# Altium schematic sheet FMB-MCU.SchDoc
size A3
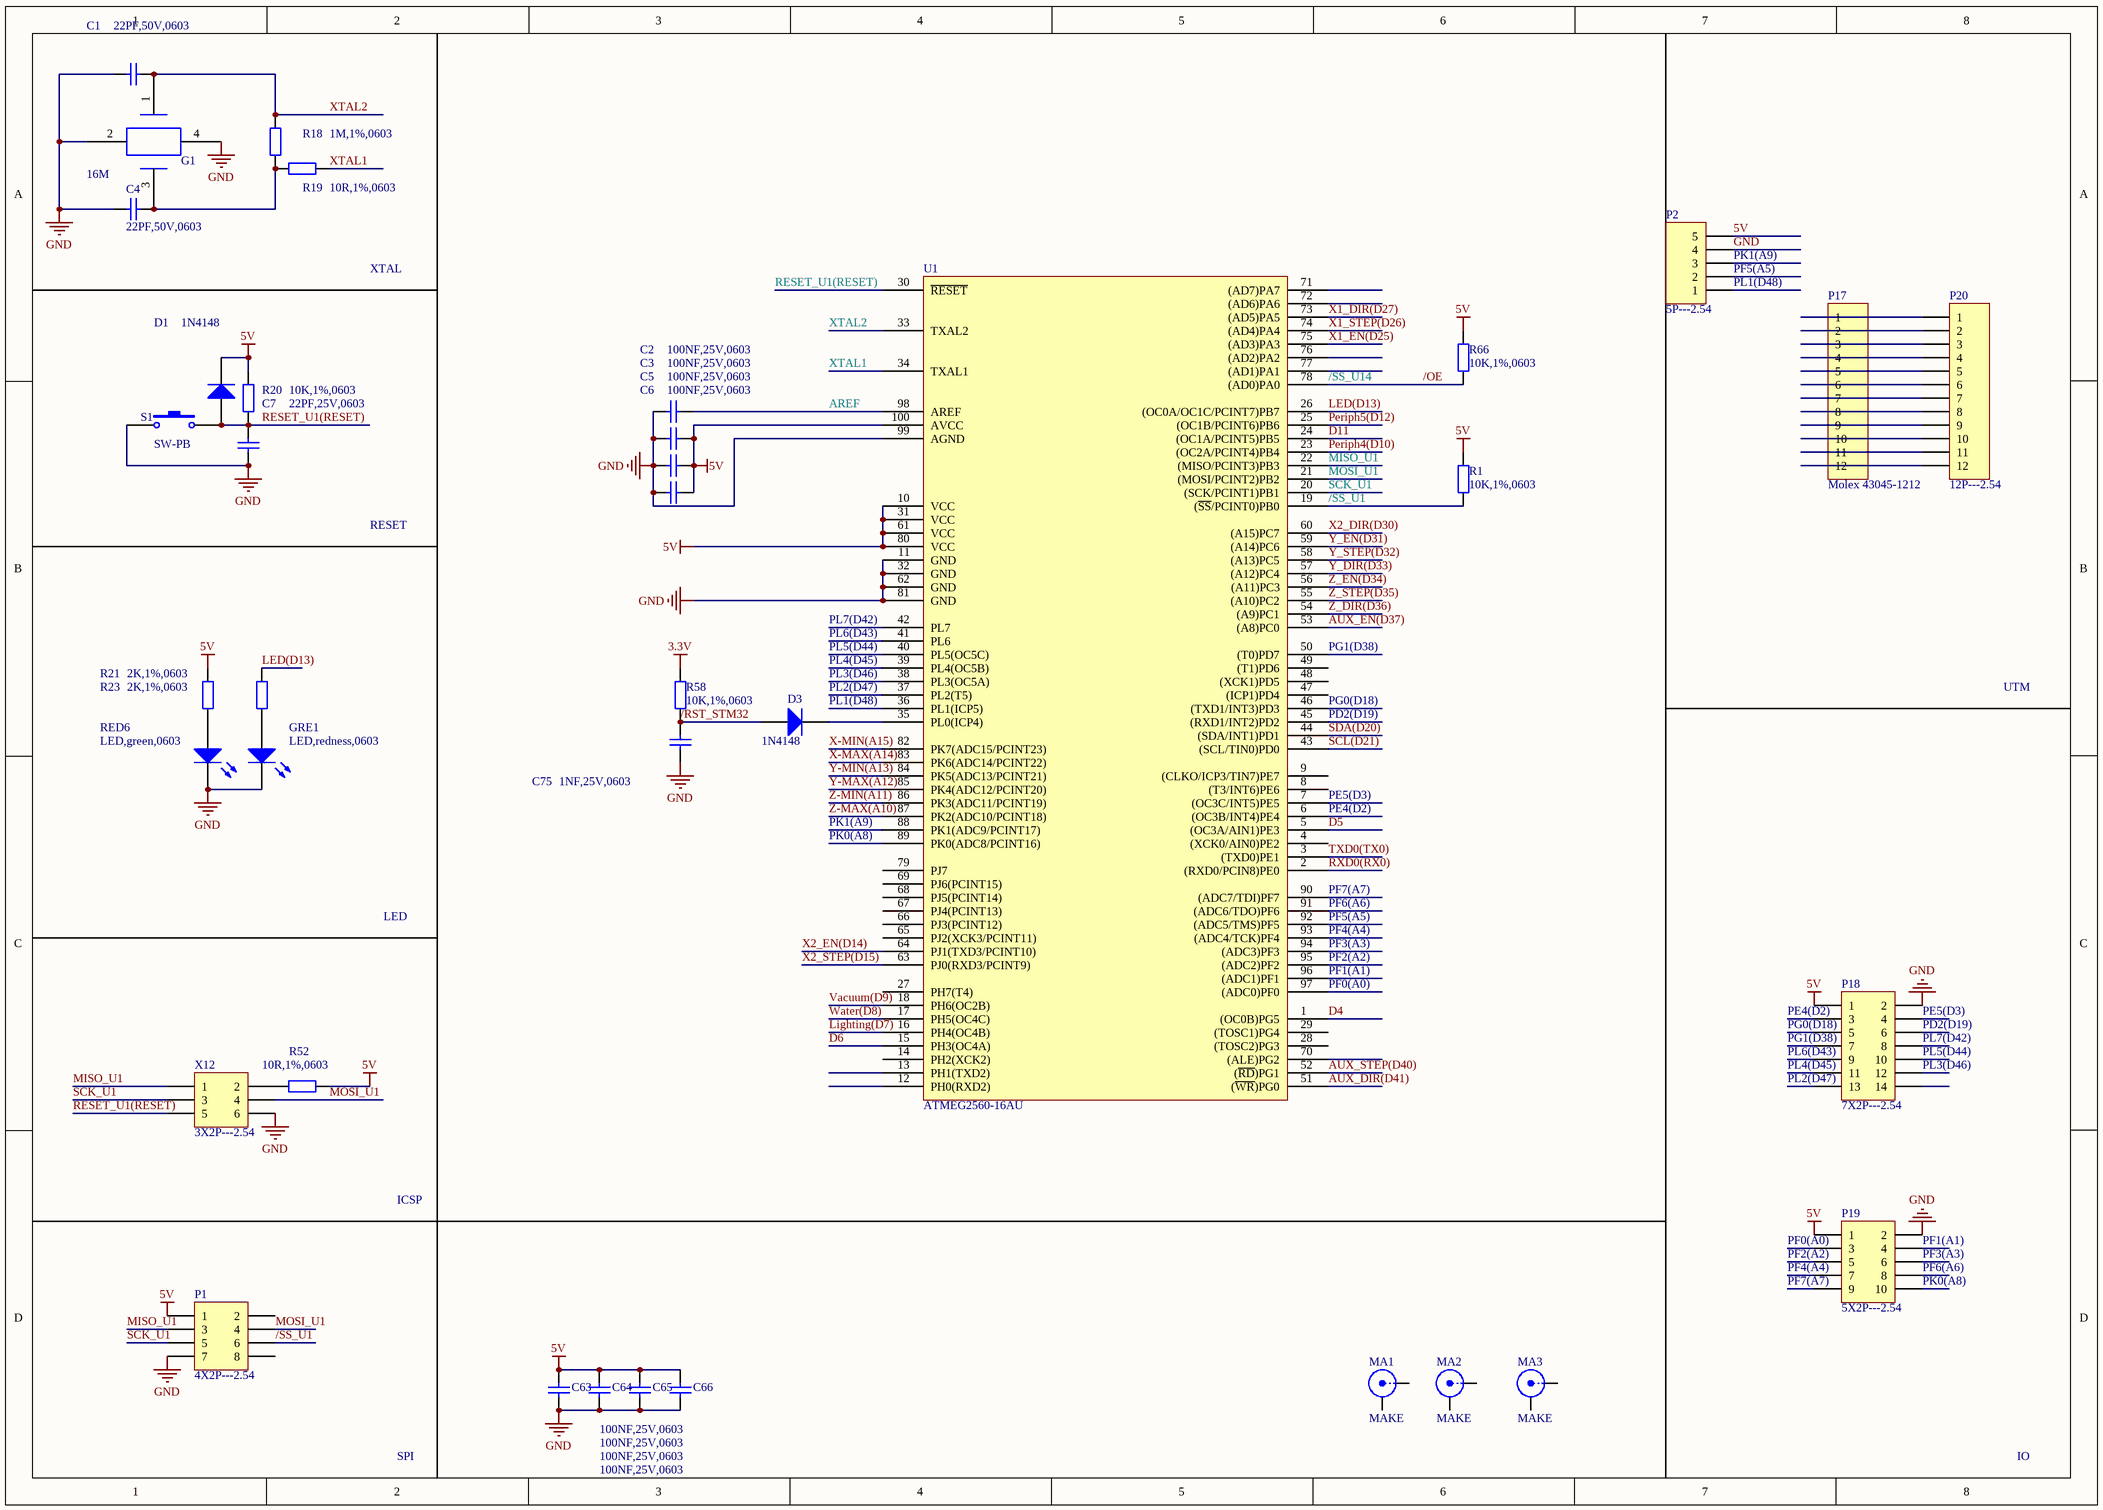
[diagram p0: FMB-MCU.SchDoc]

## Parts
C1  22PF,50V,0603  [RC0603]
C2  100NF,25V,0603  [RC0603]
C3  100NF,25V,0603  [RC0603]
C4  22PF,50V,0603  [RC0603]
C5  100NF,25V,0603  [RC0603]
C6  100NF,25V,0603  [RC0603]
C7  22PF,25V,0603  [RC0603]
C63  100NF,25V,0603  [RC0603]
C64  100NF,25V,0603  [RC0603]
C65  100NF,25V,0603  [RC0603]
C66  100NF,25V,0603  [RC0603]
C75  1NF,25V,0603  [RC0603]
D1  1N4148  [SOD-323]
D3  1N4148  [SOD-323]
G1  16M  [Y-3225]
GRE1  LED,redness,0603  [LED-0603]
MA1  MAKE
MA2  MAKE
MA3  MAKE
P1  4X2P---2.54  [HDR2X4]
P2  5P---2.54  [HDR1X5]
P17  Molex 43045-1212  [43045-1212]
P18  7X2P---2.54  [HDR2X7]
P19  5X2P---2.54  [HDR2X5]
P20  12P---2.54  [HDR1X12]
R1  10K,1%,0603  [RC0603]
R18  1M,1%,0603  [RC0603]
R19  10R,1%,0603  [RC0603]
R20  10K,1%,0603  [RC0603]
R21  2K,1%,0603  [RC0603]
R23  2K,1%,0603  [RC0603]
R52  10R,1%,0603  [RC0603]
R58  10K,1%,0603  [RC0603]
R66  10K,1%,0603  [RC0603]
RED6  LED,green,0603  [LED-0603]
S1  SW-PB  [DIP6*6]
U1  ATMEG2560-16AU  [LQFP-100]
X12  3X2P---2.54  [HDR2X3]

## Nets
3.3V: R58.1
5V: C3.1 C5.1 C6.1 C63.1 C64.1 C65.1 C66.1 D1.2(K) P1.1 P2.5 P18.1 P19.1 R1.2 R20.1 R23.1 R52.1 R66.2 U1.10(VCC) U1.31(VCC) U1.61(VCC) U1.80(VCC) U1.100(AVCC)
GND: C1.2 C2.2 C3.2 C4.1 C5.2 C6.2 C7.2 C63.2 C64.2 C65.2 C66.2 C75.1 G1.2 G1.4 GRE1.2(K) P1.7 P2.4 P18.2 P19.2 RED6.2(K) S1.1 U1.11(GND) U1.32(GND) U1.62(GND) U1.81(GND) U1.99(AGND) X12.6
/OE: R66.1 U1.78((AD0)PA0)  [also labelled /SS_U14]
/RST_STM32: C75.2 D3.1(A) R58.2
/SS_U1: P1.6 R1.1 U1.19((~{SS}/PCINT0)PB0)
AREF: C2.1 U1.98(AREF)
AUX_DIR(D41): U1.51((~{WR})PG0)
AUX_EN(D37): U1.53((A8)PC0)
AUX_STEP(D40): U1.52((~{RD})PG1)
D4: U1.1((OC0B)PG5)
D5: U1.5((OC3A/AIN1)PE3)
D6: U1.15(PH3(OC4A))
D11: U1.24((OC1A/PCINT5)PB5)
LED(D13): R21.1 U1.26((OC0A/OC1C/PCINT7)PB7)
Lighting(D7): U1.16(PH4(OC4B))
MISO_U1: P1.3 U1.22((MISO/PCINT3)PB3) X12.1
MOSI_U1: P1.4 U1.21((MOSI/PCINT2)PB2) X12.4
PD2(D19): P18.6 U1.45((RXD1/INT2)PD2)
PE4(D2): P18.3 U1.6((OC3B/INT4)PE4)
PE5(D3): P18.4 U1.7((OC3C/INT5)PE5)
Periph4(D10): U1.23((OC2A/PCINT4)PB4)
Periph5(D12): U1.25((OC1B/PCINT6)PB6)
PF0(A0): P19.3 U1.97((ADC0)PF0)
PF1(A1): P19.4 U1.96((ADC1)PF1)
PF2(A2): P19.5 U1.95((ADC2)PF2)
PF3(A3): P19.6 U1.94((ADC3)PF3)
PF4(A4): P19.7 U1.93((ADC4/TCK)PF4)
PF5(A5): P2.2 U1.92((ADC5/TMS)PF5)
PF6(A6): P19.8 U1.91((ADC6/TDO)PF6)
PF7(A7): P19.9 U1.90((ADC7/TDI)PF7)
PG0(D18): P18.5 U1.46((TXD1/INT3)PD3)
PG1(D38): P18.7 U1.50((T0)PD7)
PK0(A8): P19.10 U1.89(PK0(ADC8/PCINT16))
PK1(A9): P2.3 U1.88(PK1(ADC9/PCINT17))
PL1(D48): P2.1 U1.36(PL1(ICP5))
PL2(D47): P18.13 U1.37(PL2(T5))
PL3(D46): P18.12 U1.38(PL3(OC5A))
PL4(D45): P18.11 U1.39(PL4(OC5B))
PL5(D44): P18.10 U1.40(PL5(OC5C))
PL6(D43): P18.9 U1.41(PL6)
PL7(D42): P18.8 U1.42(PL7)
RESET_U1(RESET): C7.1 D1.1(A) R20.2 S1.2 U1.30(~{RESET}) X12.5
RXD0(RX0): U1.2((RXD0/PCIN8)PE0)
SCK_U1: P1.5 U1.20((SCK/PCINT1)PB1) X12.3
SCL(D21): U1.43((SCL/TIN0)PD0)
SDA(D20): U1.44((SDA/INT1)PD1)
TXD0(TX0): U1.3((TXD0)PE1)
Vacuum(D9): U1.18(PH6(OC2B))
Water(D8): U1.17(PH5(OC4C))
X1_DIR(D27): U1.73((AD5)PA5)
X1_EN(D25): U1.75((AD3)PA3)
X1_STEP(D26): U1.74((AD4)PA4)
X2_DIR(D30): U1.60((A15)PC7)
X2_EN(D14): U1.64(PJ1(TXD3/PCINT10))
X2_STEP(D15): U1.63(PJ0(RXD3/PCINT9))
X-MAX(A14): U1.83(PK6(ADC14/PCINT22))
X-MIN(A15): U1.82(PK7(ADC15/PCINT23))
XTAL1: R19.2 U1.34(TXAL1)
XTAL2: C1.1 G1.1 R18.1 U1.33(TXAL2)
Y-MAX(A12): U1.85(PK4(ADC12/PCINT20))
Y-MIN(A13): U1.84(PK5(ADC13/PCINT21))
Y_DIR(D33): U1.57((A12)PC4)
Y_EN(D31): U1.59((A14)PC6)
Y_STEP(D32): U1.58((A13)PC5)
Z-MAX(A10): U1.87(PK2(ADC10/PCINT18))
Z-MIN(A11): U1.86(PK3(ADC11/PCINT19))
Z_DIR(D36): U1.54((A9)PC1)
Z_EN(D34): U1.56((A11)PC3)
Z_STEP(D35): U1.55((A10)PC2)
NetC4_2: C4.2 G1.3 R18.2 R19.1
NetD3_2: D3.2(K) U1.35(PL0(ICP4))
NetGRE1_1: GRE1.1(A) R21.2
NetP17_1: P17.1 P20.1
NetP17_2: P17.2 P20.2
NetP17_3: P17.3 P20.3
NetP17_4: P17.4 P20.4
NetP17_5: P17.5 P20.5
NetP17_6: P17.6 P20.6
NetP17_7: P17.7 P20.7
NetP17_8: P17.8 P20.8
NetP17_9: P17.9 P20.9
NetP17_10: P17.10 P20.10
NetP17_11: P17.11 P20.11
NetP17_12: P17.12 P20.12
NetR23_2: R23.2 RED6.1(A)
NetR52_2: R52.2 X12.2

Not connected (* = marked no-connect by the designer): MA1 1(X) 2(Y); MA2 1(X) 2(Y); MA3 1(X) 2(Y); P1 2 8; P18 14; U1 4((XCK0/AIN0)PE2) 8((T3/INT6)PE6) 9((CLKO/ICP3/TIN7)PE7) 12(PH0(RXD2)) 13(PH1(TXD2)) 14(PH2(XCK2)) 27(PH7(T4)) 28((TOSC2)PG3) 29((TOSC1)PG4) 47((ICP1)PD4) 48((XCK1)PD5) 49((T1)PD6) 65(PJ2(XCK3/PCINT11)) 66(PJ3(PCINT12)) 67(PJ4(PCINT13)) 68(PJ5(PCINT14)) 69(PJ6(PCINT15)) 70((ALE)PG2) 71((AD7)PA7) 72((AD6)PA6) 76((AD2)PA2) 77((AD1)PA1) 79(PJ7)

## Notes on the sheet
- XTAL
- RESET
- UTM
- LED
- ICSP
- SPI
- IO

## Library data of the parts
C1-C7 C63-C66 C75 = Cap: Capacitor; Value: 100pF
D1 D3 = Diode: Default Diode
G1 = G
GRE1 RED6 = LED0: Typical INFRARED GaAs LED
MA1-MA3 = BNC: BNC Elbow Connector
P1 = Header 4X2: Header, 4-Pin, Dual row
P2 = Header 5: Header, 5-Pin
P17 P20 = Header 12: Header, 12-Pin
P18 = Header 7X2: Header, 7-Pin, Dual row
P19 = Header 5X2: Header, 5-Pin, Dual row
R1 R18-R21 R23 R52 R58 R66 = Res2: Resistor; Value: 1K
S1 = SW-PB: Switch
X12 = Header 3X2: Header, 3-Pin, Dual row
